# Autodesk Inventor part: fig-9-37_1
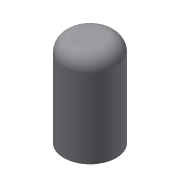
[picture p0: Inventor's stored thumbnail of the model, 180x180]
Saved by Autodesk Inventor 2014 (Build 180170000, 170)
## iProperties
Created: 2013-03
Part Number: fig-9-37_1
Material: Generic
Document SubType Name: Modeling
Designer: CADCIM
Density: 1 g/cm^3
Appearance: Default
Author: CADCIM
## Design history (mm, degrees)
sketch "Sketch1"
  geometry: C1 r 10 at (0, 0); 1 further point
  constraints: 1 centre point, 1 coincident
  dimensions: "d0" = 20 diameter of C1
extrude "Extrusion1" new body sketch "Sketch1" distance "d2" = 35; taper "d3" = 0 deg
fillet "Fillet1" dims "d4" = 5
shell "Shell1" dims "d5" = 2
body "Solid1"
